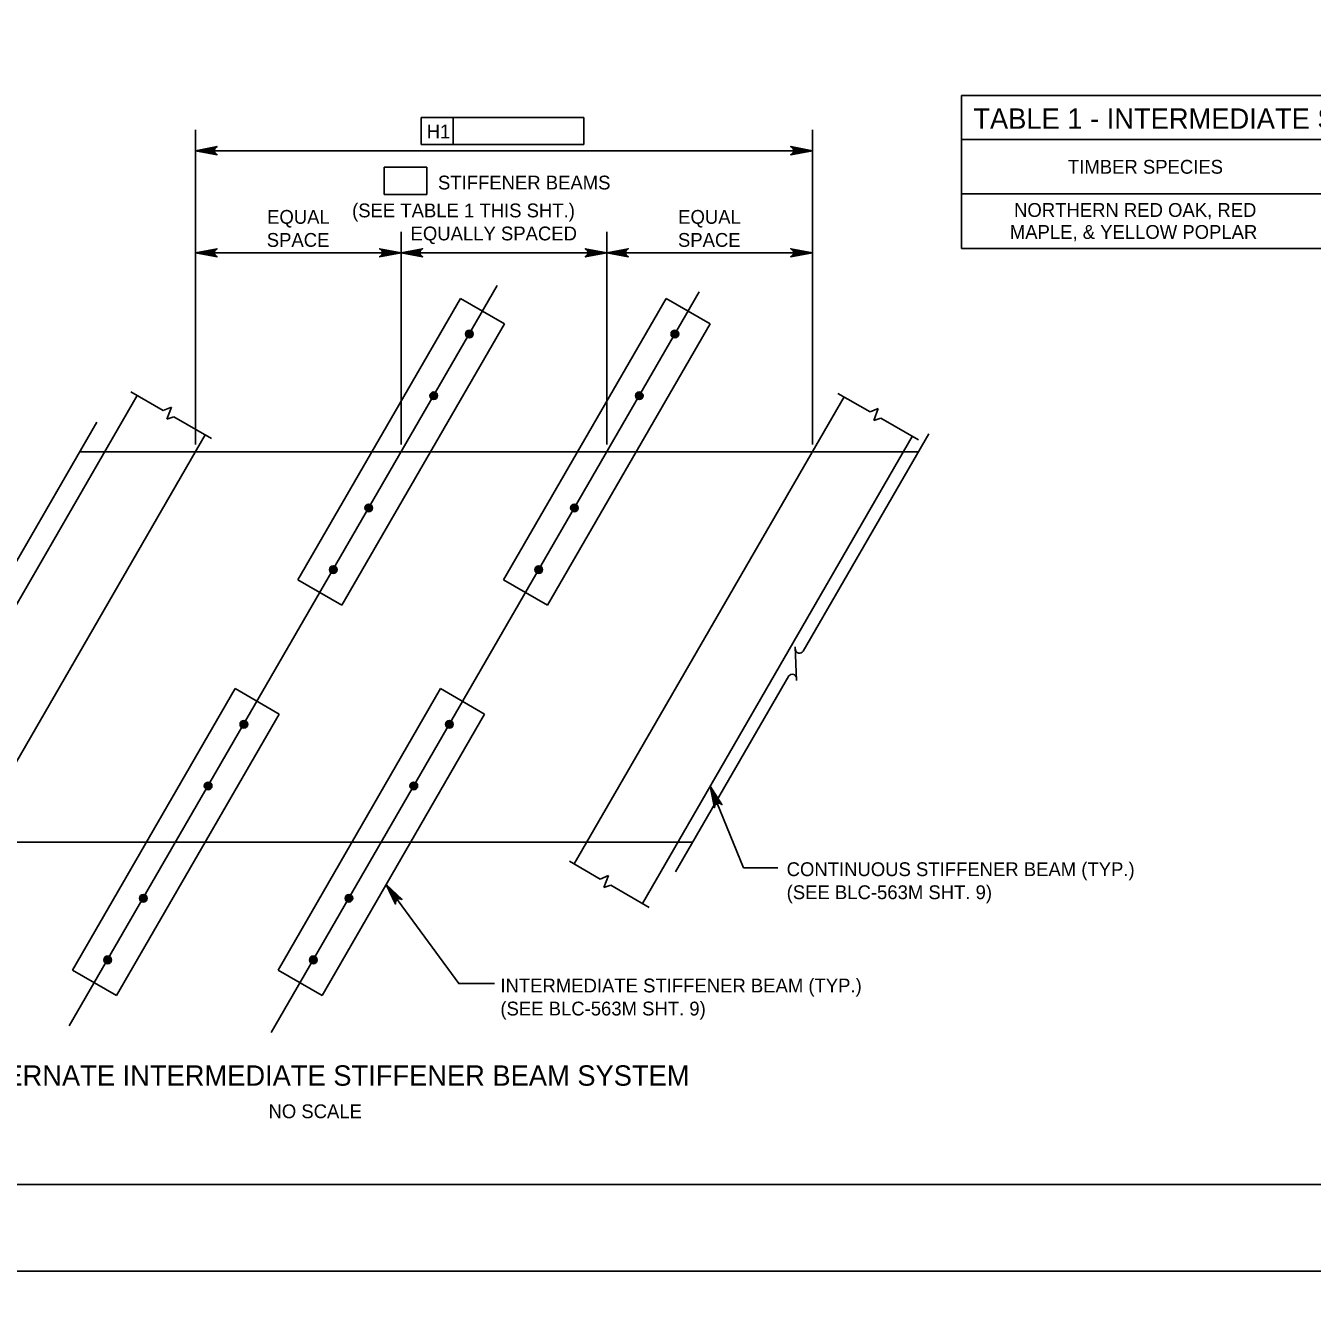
# Model space of a CAD drawing. Extents: x -8 to 75, y -110 to 0.
# Drawn here: x 48.5 to 59.67, y -22.38 to -11.19 of the extents above; entities that cross this region are included whole.
import ezdxf

# ---------------------------------------------------------------- set-up
doc = ezdxf.new("R2010")
doc.units = 0
for name, color, linetype in [('1', 7, 'Continuous'), ('2', 7, 'Continuous'), ('3', 7, 'Continuous'), ('4', 7, 'Continuous'), ('63', 7, 'Continuous'), ('8', 7, 'Continuous')]:
    doc.layers.add(name, color=color, linetype=linetype)

msp = doc.modelspace()

# ---------------------------------------------------------------- linework, layer by layer
at = {"layer": '1'}
msp.add_lwpolyline([(35.75, -21.25), (67.25, -21.25), (67.25, -0.75), (35.75, -0.75)], close=True, dxfattribs=at)
at = {"layer": '2'}
for p, q in [((48.968, -14.886), (56.251, -14.886)), ((47.01, -18.275), (54.292, -18.275))]:
    msp.add_line(p, q, dxfattribs=at)
at = {"layer": '3'}
for p, q in [((52.275, -13.555), (50.863, -15.999)), ((52.275, -13.555), (52.657, -13.775)), ((54.061, -13.555), (52.648, -15.999)), ((54.061, -13.555), (54.443, -13.775)), ((52.657, -13.775), (51.244, -16.219)), ((54.443, -13.775), (53.03, -16.219)), ((49.465, -14.397), (47.122, -18.451)), ((49.692, -14.528), (49.411, -14.366)), ((55.605, -14.41), (53.261, -18.465)), ((55.831, -14.541), (55.551, -14.379)), ((49.764, -14.498), (49.692, -14.528)), ((49.723, -14.602), (49.764, -14.498)), ((55.903, -14.512), (55.831, -14.541)), ((55.863, -14.616), (55.903, -14.512)), ((49.117, -14.629), (48.065, -16.449)), ((49.785, -14.582), (49.723, -14.602)), ((50.112, -14.771), (49.785, -14.582)), ((55.925, -14.595), (55.863, -14.616)), ((56.251, -14.784), (55.925, -14.595)), ((47.715, -18.794), (50.058, -14.74)), ((53.854, -18.808), (56.198, -14.753)), ((56.341, -14.731), (55.25, -16.618)), ((50.863, -15.999), (51.244, -16.219)), ((52.648, -15.999), (53.03, -16.219)), ((55.182, -16.581), (55.193, -16.872)), ((55.126, -16.833), (54.142, -18.535)), ((50.317, -16.943), (48.904, -19.387)), ((50.317, -16.943), (50.699, -17.164)), ((52.102, -16.943), (50.69, -19.387)), ((52.102, -16.943), (52.484, -17.164)), ((50.699, -17.164), (49.286, -19.607)), ((52.484, -17.164), (51.072, -19.607)), ((53.488, -18.596), (53.22, -18.441)), ((53.56, -18.566), (53.488, -18.596)), ((53.519, -18.67), (53.56, -18.566)), ((53.581, -18.65), (53.519, -18.67)), ((53.914, -18.842), (53.581, -18.65)), ((48.904, -19.387), (49.286, -19.607)), ((50.69, -19.387), (51.072, -19.607))]:
    msp.add_line(p, q, dxfattribs=at)
for centre, radius in [((52.351, -13.864), 0.0333), ((52.351, -13.864), 0.0295), ((52.351, -13.864), 0.025), ((52.351, -13.864), 0.0167), ((52.351, -13.864), 0.00833), ((54.136, -13.864), 0.0333), ((54.136, -13.864), 0.0295), ((54.136, -13.864), 0.025), ((54.136, -13.864), 0.0167), ((54.136, -13.864), 0.00833), ((52.042, -14.4), 0.0333), ((52.042, -14.4), 0.0295), ((52.042, -14.4), 0.025), ((52.042, -14.4), 0.0167), ((52.042, -14.4), 0.00833), ((53.827, -14.4), 0.0333), ((53.827, -14.4), 0.0295), ((53.827, -14.4), 0.025), ((53.827, -14.4), 0.0167), ((53.827, -14.4), 0.00833), ((51.478, -15.374), 0.0333), ((51.478, -15.374), 0.0295), ((51.478, -15.374), 0.025), ((51.478, -15.374), 0.0167), ((51.478, -15.374), 0.00833), ((53.264, -15.374), 0.0333), ((53.264, -15.374), 0.0295), ((53.264, -15.374), 0.025), ((53.264, -15.374), 0.0167), ((53.264, -15.374), 0.00833), ((51.169, -15.91), 0.0333), ((51.169, -15.91), 0.0295), ((51.169, -15.91), 0.025), ((52.954, -15.91), 0.0333), ((52.954, -15.91), 0.0295), ((52.954, -15.91), 0.025), ((51.169, -15.91), 0.0167), ((51.169, -15.91), 0.00833), ((52.954, -15.91), 0.0167), ((52.954, -15.91), 0.00833), ((50.393, -17.253), 0.0333), ((50.393, -17.253), 0.0295), ((50.393, -17.253), 0.025), ((52.178, -17.253), 0.0333), ((52.178, -17.253), 0.0295), ((52.178, -17.253), 0.025), ((50.393, -17.253), 0.0167), ((50.393, -17.253), 0.00833), ((52.178, -17.253), 0.0167), ((52.178, -17.253), 0.00833), ((50.083, -17.788), 0.0333), ((50.083, -17.788), 0.0295), ((50.083, -17.788), 0.025), ((50.083, -17.788), 0.0167), ((50.083, -17.788), 0.00833), ((51.869, -17.788), 0.0333), ((51.869, -17.788), 0.0295), ((51.869, -17.788), 0.025), ((51.869, -17.788), 0.0167), ((51.869, -17.788), 0.00833), ((49.52, -18.763), 0.0333), ((49.52, -18.763), 0.0295), ((49.52, -18.763), 0.025), ((49.52, -18.763), 0.0167), ((49.52, -18.763), 0.00833), ((51.305, -18.763), 0.0333), ((51.305, -18.763), 0.0295), ((51.305, -18.763), 0.025), ((51.305, -18.763), 0.0167), ((51.305, -18.763), 0.00833), ((49.21, -19.298), 0.0333), ((49.21, -19.298), 0.0295), ((49.21, -19.298), 0.025), ((49.21, -19.298), 0.0167), ((49.21, -19.298), 0.00833), ((50.996, -19.298), 0.0333), ((50.996, -19.298), 0.0295), ((50.996, -19.298), 0.025), ((50.996, -19.298), 0.0167), ((50.996, -19.298), 0.00833)]:
    msp.add_circle(centre, radius, dxfattribs=at)
for centre, start, end in [((55.219, -16.599), 179.9708, 329.9708), ((55.156, -16.854), 2.1036, 144.6422)]:
    msp.add_arc(centre, 0.0364, start, end, dxfattribs=at)
at = {"layer": '4'}
for p, q in [((51.934, -11.983), (51.934, -12.219)), ((51.934, -11.983), (53.346, -11.983)), ((52.21, -11.983), (52.21, -12.219)), ((53.346, -11.983), (53.346, -12.219)), ((49.974, -14.824), (49.974, -12.092)), ((55.33, -14.824), (55.33, -12.092)), ((55.33, -12.272), (49.974, -12.272)), ((53.346, -12.219), (51.934, -12.219)), ((51.611, -12.416), (51.982, -12.416)), ((51.611, -12.416), (51.611, -12.653)), ((51.982, -12.416), (51.982, -12.653)), ((51.982, -12.653), (51.611, -12.653)), ((49.974, -14.824), (49.974, -12.978)), ((51.759, -14.824), (51.759, -12.978)), ((53.544, -14.824), (53.544, -12.978)), ((55.33, -14.824), (55.33, -12.978)), ((51.639, -13.158), (49.974, -13.158)), ((53.424, -13.158), (51.879, -13.158)), ((53.664, -13.158), (55.33, -13.158)), ((52.593, -13.443), (48.877, -19.872)), ((54.346, -13.499), (50.63, -19.928)), ((54.732, -18.5), (55.031, -18.5)), ((52.256, -19.502), (52.569, -19.502))]:
    msp.add_line(p, q, dxfattribs=at)
for points in [[(49.974, -12.272), (50.16, -12.237), (50.146, -12.247), (50.138, -12.259), (50.136, -12.272), (50.138, -12.284), (50.146, -12.297), (50.16, -12.307), (49.974, -12.272), (50.146, -12.297), (50.138, -12.284), (49.974, -12.272), (50.136, -12.272), (50.138, -12.259), (49.974, -12.272), (50.146, -12.247)], [(55.33, -12.272), (55.143, -12.307), (55.158, -12.297), (55.165, -12.284), (55.167, -12.272), (55.165, -12.259), (55.158, -12.247), (55.143, -12.237), (55.33, -12.272), (55.158, -12.247), (55.165, -12.259), (55.33, -12.272), (55.167, -12.272), (55.165, -12.284), (55.33, -12.272), (55.158, -12.297)], [(49.974, -13.158), (50.16, -13.123), (50.146, -13.133), (50.138, -13.145), (50.136, -13.158), (50.138, -13.17), (50.146, -13.183), (50.16, -13.193), (49.974, -13.158), (50.146, -13.183), (50.138, -13.17), (49.974, -13.158), (50.136, -13.158), (50.138, -13.145), (49.974, -13.158), (50.146, -13.133)], [(51.759, -13.158), (51.572, -13.193), (51.587, -13.183), (51.594, -13.17), (51.596, -13.158), (51.594, -13.145), (51.587, -13.133), (51.572, -13.123), (51.759, -13.158), (51.587, -13.133), (51.594, -13.145), (51.759, -13.158), (51.596, -13.158), (51.594, -13.17), (51.759, -13.158), (51.587, -13.183)], [(51.759, -13.158), (51.945, -13.193), (51.931, -13.183), (51.924, -13.17), (51.921, -13.158), (51.924, -13.145), (51.931, -13.133), (51.945, -13.123), (51.759, -13.158), (51.931, -13.133), (51.924, -13.145), (51.759, -13.158), (51.921, -13.158), (51.924, -13.17), (51.759, -13.158), (51.931, -13.183)], [(53.544, -13.158), (53.358, -13.193), (53.372, -13.183), (53.38, -13.17), (53.382, -13.158), (53.38, -13.145), (53.372, -13.133), (53.358, -13.123), (53.544, -13.158), (53.372, -13.133), (53.38, -13.145), (53.544, -13.158), (53.382, -13.158), (53.38, -13.17), (53.544, -13.158), (53.372, -13.183)], [(53.544, -13.158), (53.731, -13.193), (53.716, -13.183), (53.709, -13.17), (53.707, -13.158), (53.709, -13.145), (53.716, -13.133), (53.731, -13.123), (53.544, -13.158), (53.716, -13.133), (53.709, -13.145), (53.544, -13.158), (53.707, -13.158), (53.709, -13.17), (53.544, -13.158), (53.716, -13.183)], [(55.33, -13.158), (55.143, -13.193), (55.158, -13.183), (55.165, -13.17), (55.167, -13.158), (55.165, -13.145), (55.158, -13.133), (55.143, -13.123), (55.33, -13.158), (55.158, -13.133), (55.165, -13.145), (55.33, -13.158), (55.167, -13.158), (55.165, -13.17), (55.33, -13.158), (55.158, -13.183)], [(54.442, -17.791), (54.731, -18.5)], [(54.442, -17.791), (54.545, -17.95), (54.53, -17.941), (54.516, -17.938), (54.504, -17.941), (54.493, -17.948), (54.484, -17.959), (54.48, -17.977), (54.442, -17.791), (54.484, -17.959), (54.493, -17.948), (54.442, -17.791), (54.504, -17.941), (54.516, -17.938), (54.442, -17.791), (54.53, -17.941)], [(51.629, -18.643), (52.26, -19.503)], [(51.629, -18.643), (51.767, -18.773), (51.751, -18.767), (51.736, -18.769), (51.725, -18.774), (51.716, -18.784), (51.71, -18.797), (51.711, -18.814), (51.629, -18.643), (51.71, -18.797), (51.716, -18.784), (51.629, -18.643), (51.725, -18.774), (51.736, -18.769), (51.629, -18.643), (51.751, -18.767)]]:
    msp.add_lwpolyline(points, dxfattribs=at)
for points in [[(50.093, -12.252), (50.093, -12.292), (49.974, -12.272)], [(55.21, -12.252), (55.21, -12.292), (55.33, -12.272)], [(50.093, -13.138), (50.093, -13.178), (49.974, -13.158)], [(51.639, -13.138), (51.639, -13.178), (51.759, -13.158)], [(51.879, -13.138), (51.879, -13.178), (51.759, -13.158)], [(53.424, -13.138), (53.424, -13.178), (53.544, -13.158)], [(53.664, -13.138), (53.664, -13.178), (53.544, -13.158)], [(55.21, -13.138), (55.21, -13.178), (55.33, -13.158)], [(54.442, -17.791), (54.478, -17.906), (54.497, -17.898)], [(51.629, -18.643), (51.692, -18.746), (51.708, -18.734)]]:
    msp.add_lwpolyline(points, close=True, dxfattribs=at)
at = {"layer": '63'}
for points in [[(34, -22), (68, -22), (68, 0), (34, 0)], [(34, -44), (68, -44), (68, -22), (34, -22)]]:
    msp.add_lwpolyline(points, close=True, dxfattribs=at)
at = {"layer": '8'}
for p, q in [((56.624, -11.794), (65.512, -11.794)), ((56.624, -11.794), (56.624, -13.12)), ((56.624, -12.175), (65.512, -12.175)), ((56.624, -12.648), (65.512, -12.648)), ((56.624, -13.12), (65.512, -13.12))]:
    msp.add_line(p, q, dxfattribs=at)

# ---------------------------------------------------------------- texts
at = {"layer": '4'}
for s, height, p in [('TABLE 1 - INTERMEDIATE STIFFENER BEAM DESIGN DATA', 0.17717, (56.728, -12.082)), ('H1', 0.12, (51.981, -12.165)), ('TIMBER SPECIES', 0.12, (57.55, -12.472)), ('STIFFENER BEAMS', 0.12, (52.079, -12.609)), ('(SEE TABLE 1 THIS SHT.)', 0.12, (51.333, -12.851)), ('NORTHERN RED OAK, RED', 0.12, (57.082, -12.847)), ('EQUAL', 0.12, (50.595, -12.907)), ('EQUAL', 0.12, (54.165, -12.907)), ('EQUALLY SPACED', 0.12, (51.841, -13.051)), ('MAPLE, & YELLOW POPLAR', 0.12, (57.045, -13.038)), ('SPACE', 0.12, (50.592, -13.107)), ('SPACE', 0.12, (54.163, -13.107)), ('CONTINUOUS STIFFENER BEAM (TYP.)', 0.12, (55.107, -18.571)), ('(SEE BLC-563M SHT. 9)', 0.12, (55.107, -18.771)), ('INTERMEDIATE STIFFENER BEAM (TYP.)', 0.12, (52.621, -19.581)), ('(SEE BLC-563M SHT. 9)', 0.12, (52.621, -19.781)), ('PLAN VIEW OF ALTERNATE INTERMEDIATE STIFFENER BEAM SYSTEM', 0.17717, (46.128, -20.391)), ('NO SCALE', 0.12, (50.607, -20.673))]:
    msp.add_text(s, height=height, dxfattribs=at).set_placement(p)

doc.saveas('drawing.dxf')
